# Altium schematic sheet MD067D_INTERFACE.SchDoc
size 431 x 279 mm; Date: Not shown in title block; ApprovedBy: Not shown in title block; CheckedBy: Not shown in title block; Author: Not shown in title block; CompanyName: Not shown in title block; Engineer: Not shown in title block; Organization: Not shown in title block; Address1: Not shown in title block; Address2: Not shown in title block; Address3: Not shown in title block; Address4: Not shown in title block; DocumentNumber: 1; Revision: Use project parameter SCH_Rev; SheetNumber: 1; SheetTotal: 5; PageSetup: Record=PageOptions¦CenterHorizontal=True¦CenterVertical=True¦PrintScale=1.00¦XCorrection=1.00¦YCorrection=1.00¦PrintKind=0¦BorderSize=5000000¦LeftOffset=0¦BottomOffset=0¦Orientation=2¦PaperLength=1000¦PaperWidth=1000¦Scale=100¦PaperSource=15¦PrintQuality=600¦MediaType=1¦DitherType=10¦PaperKind=Letter¦PrintScaleMode=1
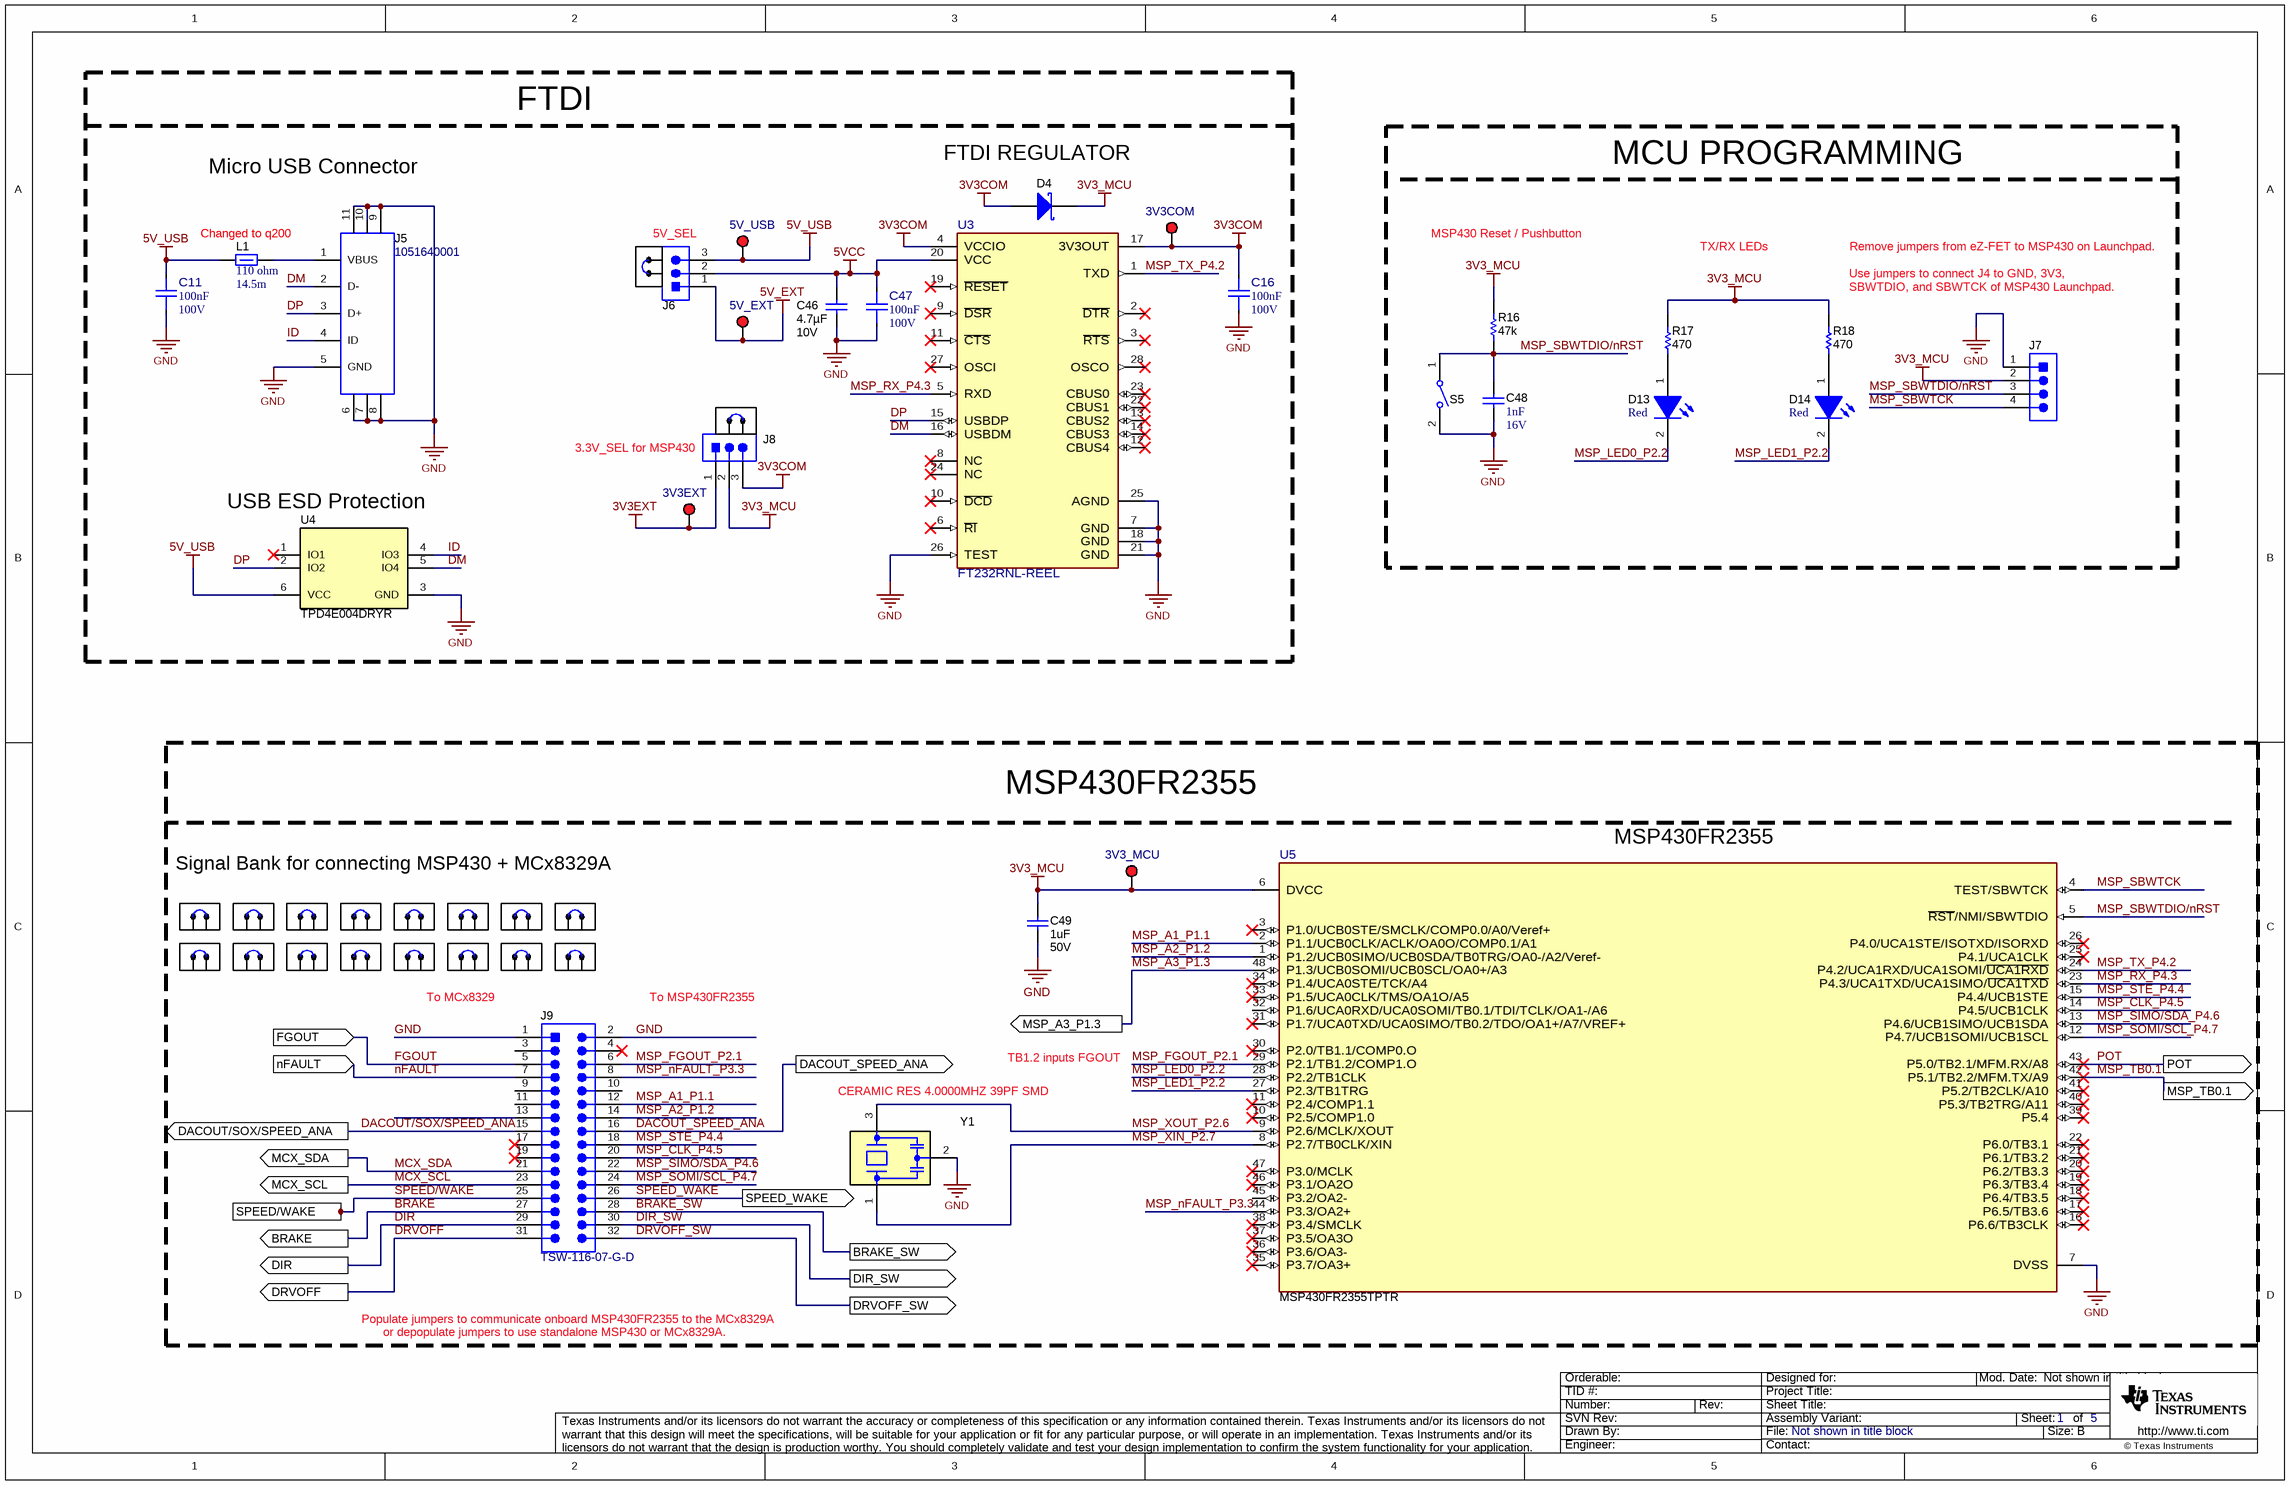
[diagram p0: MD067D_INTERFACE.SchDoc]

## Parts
C11  Cap_F: 100nF  VDC_V: 100V  [FP-885012206120_0603-MFG]  (hidden comment: 885012206120)
C16  Cap_F: 100nF  VDC_V: 100V  [FP-885012206120_0603-MFG]  (hidden comment: 885012206120)
C46  Cap_F: 4.7µF  VDC_V: 10V  [0603L]  (hidden comment: GRM188Z71A475ME15D)
C47  Cap_F: 100nF  VDC_V: 100V  [FP-885012206120_0603-MFG]  (hidden comment: 885012206120)
C48  Cap_F: 1nF  VDC_V: 16V  [0603L]  (hidden comment: 885012206034)
C49  ValueDisplayed: 1uF  VDC_V: 50V  [0805L]  (hidden comment: 885012207103)
D4  BAT165E6327HTSA1  [SOD-323]  (value not drawn)
D13  Color: Red  [FP-150060RS75003_0603-MFG]  (hidden comment: 150060RS75003)
D14  Color: Red  [FP-150060RS75003_0603-MFG]  (hidden comment: 150060RS75003)
J5  1051640001  [Molex_1051640001]
J6  61300311121  [WURTH_61300311121]  (value not drawn)
J7  61300411121  [WURTH_61300411121]  (value not drawn)
J8  61300311121  [WURTH_61300311121]  (value not drawn)
J9  TSW-116-07-G-D  [TSW-116-07-G-D]
L1  ValueDisplayed: 110 ohm  DCR_ohm: 14.5m  [0603]  (hidden comment: 74279228111)
R16  ValueDisplayed: 47k  [0603L]  (hidden comment: RC0603JR-0747KL)
R17  ValueDisplayed: 470  [0603L]  (hidden comment: RC0603JR-07470RL)
R18  ValueDisplayed: 470  [0603L]  (hidden comment: RC0603JR-07470RL)
S5  SW_SPST-single  [SW_434121025816]  (value not drawn)
SH-J4  60900213421  [Wurth_60900213421]  (value not drawn)
SH-J5  60900213421  [Wurth_60900213421]  (value not drawn)
SH-J6  60900213421  [Wurth_60900213421]  (value not drawn)
SH-J10  60900213421  [Wurth_60900213421]  (value not drawn)
SH-J11  60900213421  [Wurth_60900213421]  (value not drawn)
SH-J12  60900213421  [Wurth_60900213421]  (value not drawn)
SH-J13  60900213421  [Wurth_60900213421]  (value not drawn)
SH-J14  60900213421  [Wurth_60900213421]  (value not drawn)
SH-J15  60900213421  [Wurth_60900213421]  (value not drawn)
SH-J16  60900213421  [Wurth_60900213421]  (value not drawn)
SH-J17  60900213421  [Wurth_60900213421]  (value not drawn)
SH-J18  60900213421  [Wurth_60900213421]  (value not drawn)
SH-J19  60900213421  [Wurth_60900213421]  (value not drawn)
SH-J20  60900213421  [Wurth_60900213421]  (value not drawn)
SH-J21  60900213421  [Wurth_60900213421]  (value not drawn)
SH-J22  60900213421  [Wurth_60900213421]  (value not drawn)
SH-J23  60900213421  [Wurth_60900213421]  (value not drawn)
SH-J24  60900213421  [Wurth_60900213421]  (value not drawn)
TP41  3V3COM  [Keystone5000]
TP42  5V_USB  [Keystone5000]
TP43  5V_EXT  [Keystone5000]
TP44  3V3EXT  [Keystone5000]
TP45  3V3_MCU  [Keystone5000]
U3  FT232RNL-REEL  [FP-FT232RNL-REEL_SSOP28-MFG]
U4  TPD4E004DRYR  [DRY0006A]
U5  MSP430FR2355TPTR  [PT0048A-MFG]
Y1  CSTCR4M00G55B-R0  [Murata_CSTCR_G]  (value not drawn)

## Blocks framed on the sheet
FTDI: C11 C16 C46 C47 D4 J5 J6 J8 L1 SH-J4 SH-J5 TP41-TP44 U3 U4
MCU PROGRAMMING: C48 D13 D14 J7 R16-R18 S5
MSP430FR2355: C49 J9 SH-J6 SH-J10-SH-J24 TP45 U5 Y1

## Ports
BRAKE (out), BRAKE_SW (out), DACOUT/SOX/SPEED_ANA (out), DACOUT_SPEED_ANA (out), DIR (out), DIR_SW (out), DRVOFF (out), DRVOFF_SW (out), FGOUT (in), MCX_SCL (out), MCX_SDA (out), MSP_A3_P1.3 (out), MSP_TB0.1 (out), nFAULT (in), POT (out), SPEED/WAKE (out), SPEED_WAKE (out)

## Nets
3V3_MCU: C49.1 D4.1(K) J7.2 J8.2 R16.2 R17.2 R18.2 TP45.1 U5.6(DVCC)
3V3COM: C16.2 D4.2(A) J8.3 TP41.1 U3.4(VCCIO) U3.17(3V3OUT)
3V3EXT: J8.1 TP44.1
5V_EXT: J6.1 TP43.1
5V_USB: C11.2 J6.3 L1.1 TP42.1 U4.6(VCC)
5VCC: C46.2 C47.2 J6.2 U3.20(VCC)
GND: C11.1 C16.1 C46.1 C47.1 C48.2 C49.2 J5.5(GND) J5.6 J5.7 J5.8 J5.9 J5.10 J5.11 J7.1 J9.1 J9.2 S5.2 U3.7(GND) U3.18(GND) U3.21(GND) U3.25(AGND) U3.26(TEST) U4.3(GND) U5.7(DVSS) Y1.2(GND)
BRAKE: J9.27 ; port BRAKE
BRAKE_SW: J9.28 ; port BRAKE_SW
DACOUT/SOX/SPEED_ANA: J9.15 ; port DACOUT/SOX/SPEED_ANA
DACOUT_SPEED_ANA: J9.16 ; port DACOUT_SPEED_ANA
DIR: J9.29 ; port DIR
DIR_SW: J9.30 ; port DIR_SW
DM: J5.2(D-) U3.16(USBDM) U4.5(IO4)
DP: J5.3(D+) U3.15(USBDP) U4.2(IO2)
DRVOFF: J9.31 ; port DRVOFF
DRVOFF_SW: J9.32 ; port DRVOFF_SW
FGOUT: J9.5 ; port FGOUT
ID: J5.4(ID) U4.4(IO3)
MCX_SCL: J9.23 ; port MCX_SCL
MCX_SDA: J9.21 ; port MCX_SDA
MSP_A1_P1.1: J9.12 U5.2(P1.1/UCB0CLK/ACLK/OA0O/COMP0.1/A1)
MSP_A2_P1.2: J9.14 U5.1(P1.2/UCB0SIMO/UCB0SDA/TB0TRG/OA0-/A2/Veref-)
MSP_A3_P1.3: U5.48(P1.3/UCB0SOMI/UCB0SCL/OA0+/A3) ; port MSP_A3_P1.3
MSP_CLK_P4.5: J9.20 U5.14(P4.5/UCB1CLK)
MSP_FGOUT_P2.1: J9.6 U5.29(P2.1/TB1.2/COMP1.O)
MSP_LED0_P2.2: D13.2(K) U5.28(P2.2/TB1CLK)
MSP_LED1_P2.2: D14.2(K) U5.27(P2.3/TB1TRG)
MSP_nFAULT_P3.3: J9.8 U5.44(P3.3/OA2+)
MSP_RX_P4.3: U3.5(RXD) U5.23(P4.3/UCA1TXD/UCA1SIMO/~{UCA1TXD})
MSP_SBWTCK: J7.4 U5.4(TEST/SBWTCK)
MSP_SBWTDIO/nRST: C48.1 J7.3 R16.1 S5.1 U5.5(~{RST}/NMI/SBWTDIO)
MSP_SIMO/SDA_P4.6: J9.22 U5.13(P4.6/UCB1SIMO/UCB1SDA)
MSP_SOMI/SCL_P4.7: J9.24 U5.12(P4.7/UCB1SOMI/UCB1SCL)
MSP_STE_P4.4: J9.18 U5.15(P4.4/UCB1STE)
MSP_TB0.1: U5.42(P5.1/TB2.2/MFM.TX/A9) ; port MSP_TB0.1
MSP_TX_P4.2: U3.1(TXD) U5.24(P4.2/UCA1RXD/UCA1SOMI/~{UCA1RXD})
MSP_XIN_P2.7: U5.8(P2.7/TB0CLK/XIN) Y1.1(In)
MSP_XOUT_P2.6: U5.9(P2.6/MCLK/XOUT) Y1.3(Out)
nFAULT: J9.7 ; port nFAULT
POT: U5.43(P5.0/TB2.1/MFM.RX/A8) ; port POT
SPEED/WAKE: J9.25 ; port SPEED/WAKE
SPEED_WAKE: J9.26 ; port SPEED_WAKE
NetD13_1: D13.1(A) R17.1
NetD14_1: D14.1(A) R18.1
NetJ5_1: J5.1(VBUS) L1.2

Not connected (* = marked no-connect by the designer): J9 3 4* 9 10 11 13 17* 19*; U3 2(~{DTR})* 3(~{RTS})* 6(~{RI})* 8(NC)* 9(~{DSR})* 10(~{DCD})* 11(~{CTS})* 12(CBUS4)* 13(CBUS2)* 14(CBUS3)* 19(~{RESET})* 22(CBUS1)* 23(CBUS0)* 24(NC)* 27(OSCI)* 28(OSCO)*; U4 1(IO1)*; U5 3(P1.0/UCB0STE/SMCLK/COMP0.0/A0/Veref+)* 10(P2.5/COMP1.0)* 11(P2.4/COMP1.1)* 16(P6.6/TB3CLK)* 17(P6.5/TB3.6)* 18(P6.4/TB3.5)* 19(P6.3/TB3.4)* 20(P6.2/TB3.3)* 21(P6.1/TB3.2)* 22(P6.0/TB3.1)* 25(P4.1/UCA1CLK)* 26(P4.0/UCA1STE/ISOTXD/ISORXD)* 30(P2.0/TB1.1/COMP0.O)* 31(P1.7/UCA0TXD/UCA0SIMO/TB0.2/TDO/OA1+/A7/VREF+)* 32(P1.6/UCA0RXD/UCA0SOMI/TB0.1/TDI/TCLK/OA1-/A6) 33(P1.5/UCA0CLK/TMS/OA1O/A5)* 34(P1.4/UCA0STE/TCK/A4)* 35(P3.7/OA3+)* 36(P3.6/OA3-)* 37(P3.5/OA3O)* 38(P3.4/SMCLK)* 39(P5.4)* 40(P5.3/TB2TRG/A11)* 41(P5.2/TB2CLK/A10)* 45(P3.2/OA2-) 46(P3.1/OA2O)* 47(P3.0/MCLK)*

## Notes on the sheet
- Micro USB Connector
- (near D4) FTDI REGULATOR
- (near L1) Changed to q200
- 5V_SEL
- MSP430 Reset / Pushbutton
- TX/RX LEDs
- (near R18) Use jumpers to connect J4 to GND, 3V3,
- SBWTDIO, and SBWTCK of MSP430 Launchpad.
- Remove jumpers from eZ-FET to MSP430 on Launchpad.
- (near U4) USB ESD Protection
- (near J8) 3.3V_SEL for MSP430
- (near U5) MSP430FR2355
- Signal Bank for connecting MSP430 + MCx8329A
- To MCx8329
- To MSP430FR2355
- (near Y1) CERAMIC RES 4.0000MHZ 39PF SMD
- TB1.2 inputs FGOUT
- or depopulate jumpers to use standalone MSP430 or MCx8329A.
- Populate jumpers to communicate onboard MSP430FR2355 to the MCx8329A

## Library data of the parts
C11 C16 C47 = CMP-0097294-1: 0.1 µF ±10% 100V Ceramic Capacitor X7R 0603 (1608 Metric); Manufacturer: Wurth Electronics; TempCo: 15%; Value: 100nF; SizeZ_mm: 0.87mm; AEC Qualified: No
C46 = CMP-0007498-4: CAP, CERM, 4.7 uF, 10 V, +/- 20%, X7R, 0603; Manufacturer: MuRata; TaMin_C: -55°C; Polarized: N; SizeAreaWB_mm2: 4.68; Value1: Unknown; U/M: EA; Value: 4.7uF; TaMax_C: 125°C; SizeZ_mm: 1; SizeX_mm: 1.6; SizeY_mm: 0.8; Cap_Case: 0603; SizeArea_mm2: 1.28; AEC Category: Q200
C48 = CMP-0006826-4: CAP, CERM, 1000 pF, 16 V, +/- 10%, X7R, 0603; Manufacturer: Wurth Elektronik; TaMin_C: -55°C; Polarized: N; SizeAreaWB_mm2: 4.68; Value1: Unknown; U/M: EA; Value: 1000pF; TaMax_C: 125°C; SizeZ_mm: 1; SizeX_mm: 1.6; SizeY_mm: 0.8; Cap_Case: 0603; SizeArea_mm2: 1.28; AEC Category: Q200
C49 = CMP-0007696-2: CAP, CERM, 1 uF, 50 V, +/- 10%, X7R, 0805; Manufacturer: Wurth Elektronik; Polarized: N; CompType: Capacitor; Value: 1uF; U/M: EA; Cap_F: 1µF; Value1: Unknown; TaMin_C: -55°C; TaMax_C: 125°C; Cap_Case: 0805; SizeArea_mm2: 2.5; SizeAreaWB_mm2: 6.75; SizeX_mm: 2; SizeY_mm: 1.25; SizeZ_mm: 1.45; AEC Category: Q200
D4 = CMP-0028882-2: Diode, Schottky, 40 V, 0.75 A, AEC-Q101, SOD-323; Manufacturer: Infineon Technologies; Vf_V: 740mV; Value: 40V; Value1: 0.75A; Value2: 0.74V; Io_A: 750mA; TJmax_C: 150°C; AEC Category: Q101; AEC Qualified: Y; Green_Lifecycle: Not Set; Green_REACh: Incomplete; SizeArea_mm2: 3.645; SizeAreaWB_mm2: 8.695; SizeX_mm: 2.7; SizeY_mm: 1.35; SizeZ_mm: 1
D13 D14 = CMP-0121278-2: Red 625nm LED Indication - Discrete 2V 0603 (1608 Metric); Manufacturer: Wurth Electronics; SizeZ_mm: 0.8mm; Angle: 140°; Power_TotalModule: 78mW; LambdaP: 630nm; Tjmax_C: 125°C; Vr_V: 5V; AEC Qualified: No; Forward Current: 20mA; Led Orientation: Top View; Luminous Intensity: 530mcd
J5 = CMP-0055311-1: Receptacle, USB 2.0, Micro B, 5 Position, R/A, SMT; Manufacturer: Molex; CNHeader: FALSE; Current_A: 1.8A; Gender: Female; Voltage_V: 30V; Pitch_mm: 0.65; ContactFinish: Gold; CT: TRUE; Cert_UL: Y
J6 J8 = CMP-0054796-4: Header, 2.54 mm, 3x1, Gold, TH; Manufacturer: Wurth Elektronik; CNHeader: TRUE; CT: FALSE; Green_Lifecycle: Active; Green_REACh: Passed
J7 = CMP-0054798-2: Header, 2.54 mm, 4x1, Gold, TH; Manufacturer: Wurth Elektronik; Pitch_mm: 2.54; Gender: Male; Cert_UL: Y; Shrouded: N; Row_Count: 1
J9 = CMP-0075429-1: Header, 100mil, 16x2, Gold, TH; Manufacturer: Samtec; Pitch_mm: 2.54; Cert_VDE: N; Gender: Male; Cert_CSA: Y; Voltage_V: 550V; Green_REACh: Passed; Current_A: 6.3A; CT: False; Green_Lifecycle: Active; Row_Count: 2; CNHeader: True
L1 = CMP-0003154-2: Ferrite Bead, 110 ohm @ 100 MHz, 4.1 A, 0603; Manufacturer: Wurth Elektronik; SizeX_mm: 1.6; Value: 110 ohm; Value2: 4.1A; Value1: 0.0145 ohm; SizeZ_mm: 1; SizeY_mm: 0.8; SizeAreaWB_mm2: 4.68; SizeArea_mm2: 1.28; Ztyp@1GHz_Ohm: 51.875; ZTyp@100MHz_Ohm: 110
R16 = CMP-0025925-5: RES, 47 k, 5%, 0.1 W, 0603; Manufacturer: Yageo; Power_W: 100mW; TempCo: 100 ppm/C; Value_Code: 47k0; Value: 47k; EIA_Code: E24; SizeX_mm: 1.6; SizeY_mm: 0.8; SizeZ_mm: 1; Value2: 0.1W; SizeArea_mm2: 1.28; AEC Qualified: N; VDC_V: 75V; AEC Category: Q200; SizeAreaWB_mm2: 4.68
R17 R18 = CMP-0025924-5: RES, 470, 5%, 0.1 W, 0603; Manufacturer: Yageo; Power_W: 100mW; TempCo: 100 ppm/C; Value_Code: 470R; Value: 470; EIA_Code: E24; SizeX_mm: 1.6; SizeY_mm: 0.8; SizeZ_mm: 1; Value2: 0.1W; SizeArea_mm2: 1.28; AEC Qualified: N; VDC_V: 75V; AEC Category: Q200; SizeAreaWB_mm2: 4.68
S5 = CMP-0002196-2: Switch, Tactile, SPST, 12 V, SMD; PartNumber: 434121025816; Manufacturer: Wurth Elektronik; VDC_V: 12V; SwitchFunction: Off-On; PositionCount: 1; CurrentRating_mA: 50A
SH-J4-SH-J6 SH-J10-SH-J24 = CMP-0003761-2: Shunt, 2.54mm, Gold, Black; Manufacturer: Wurth Elektronik; Value: 1x2
TP41-TP45 = CMP-0055137-1: Test Point, Miniature, Red, TH; PartNumber: 5000; Manufacturer: Keystone; ContactFinish: Silver; CNHeader: FALSE; CT: TRUE; Green_Lifecycle: Active; Green_REACh: Passed
U3 = CMP-0121693-1: UART Interface IC USB Full Speed to Serial UART IC, Includes Oscillator and EEPROM, SSOP-28; Manufacturer: FTDI; SizeZ_mm: 2mm; AEC Qualified: No; Data Rate: 3Mbits/s; Interface: UART,USB; Max Supply Voltage: 5.25V; Min Supply Voltage: 1.8V; Nominal Supply Current: 7mA; Number Of Ports: 1; Standoff Height: 0.05mm; TaMax_C: +85°C; TaMin_C: -40°C; Usb Standard: USB 2.0
U4 = CMP-0043115-3: 4-Channel ESD Protection Array for High-Speed Data Interfaces, DRY0006A (USON-6); Manufacturer: Texas Instruments; IO Leakage Current(nA): 1; USB High Speed: TRUE; IO Capacitance(Typ)(pF): 1.6; Eco-Plan: Green (RoHS & no Sb/Br); IEC 61000-4-2 Contact(+/- kV): 8; Breakdown Voltage(Min)(V): 6; IEC 61000-4-2 Air-Gap(+/- kV): 12; AEC Category: Q200; AEC Qualified: N; CompType: IC; SizeAreaWB_mm2: 4.9; SizeArea_mm2: 1.45; SizeX_mm: 1.0; SizeZ_mm: 0.6; Rating: Catalog
U5 = CMP-0089204-1: CPU16 MSP430™ FRAM Microcontroller IC 16-Bit 24MHz 32KB (32K x 8) FRAM 48-LQFP (7x7); Manufacturer: Texas Instruments; Memory Type: OTHER; Data Bus Width: 16bits; Number Of Spi Channels: 4; Number Of I/Os: 44; Number Of Uart Channels: 2; AEC Qualified: No; Standoff Height: 0.05mm; Ram Size: 4KBytes; TaMin_C: -40°C; Core Architecture: RISC; Number Of Adc Channels: 12; SizeZ_mm: 1.6mm; Number Of A/D Converters: 1; Memory Size: 32KBytes; TaMax_C: +105°C; TJmax_C: +115°C; Interface: I2C,SPI,UART,USART,SCI,IrDA; Min Supply Voltage: 1.8V; Max Supply Voltage: 3.6V
Y1 = CMP-0084387-1: Resonator, 4 MHz, 39 pF, AEC-Q200 Grade 1, SMD; Manufacturer: MuRata; Load Capacitance: 39 pF; AEC Qualified: Y; TaMax_C: 125°C; AEC Category: Q200; SizeArea_mm2: 9; SizeZ_mm: 1.2; Frequency_Fixed: 4MHz; SizeAreaWB_mm2: 16.5; SizeY_mm: 2; SizeX_mm: 4.5; TaMin_C: -40°C; AEC Grade: 1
